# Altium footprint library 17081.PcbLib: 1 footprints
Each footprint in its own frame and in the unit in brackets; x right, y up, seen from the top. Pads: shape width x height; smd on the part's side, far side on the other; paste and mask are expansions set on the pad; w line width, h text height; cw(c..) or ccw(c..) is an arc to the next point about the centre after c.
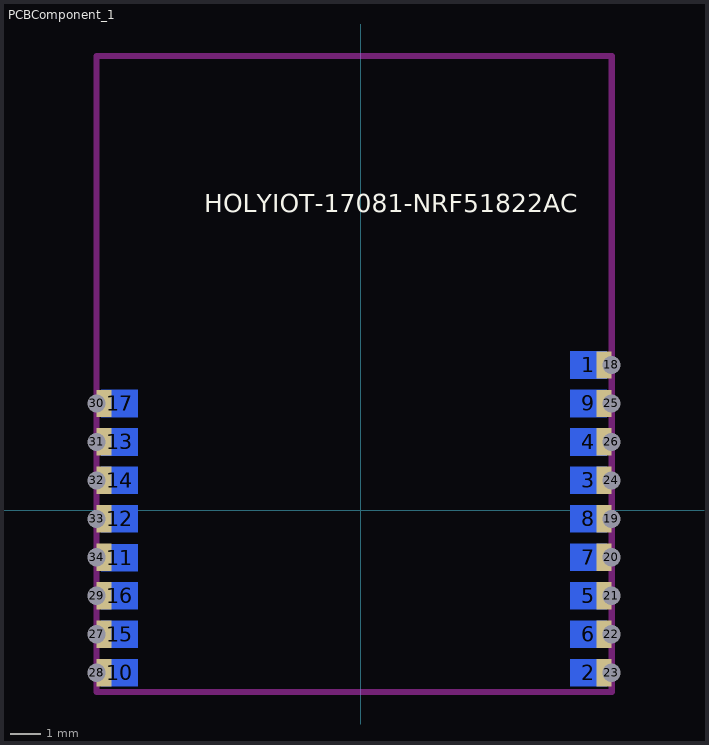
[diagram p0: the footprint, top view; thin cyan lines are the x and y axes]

## PCBComponent_1 [mm]
pads (34):
  rect 1.2x0.9 smd far side: 1(7.516,4.802) 2(7.516,-5.358) 3(7.516,0.992) 4(7.516,2.262) 5(7.516,-2.818) 6(7.516,-4.088) 7(7.516,-1.548) 8(7.516,-0.278) 9(7.516,3.532) 10(-7.954,-5.358) 11(-7.954,-1.558) 12(-7.954,-0.278) 13(-7.954,2.262) 14(-7.954,0.992) 15(-7.954,-4.088) 16(-7.954,-2.818) 17(-7.954,3.532)
  rect 0.5x0.9 hole 0.6 copper offset -0.25,0: 18(8.276,4.802) 19(8.276,-0.278) 20(8.276,-1.548) 21(8.276,-2.818) 22(8.276,-4.088) 23(8.276,-5.358) 24(8.276,0.992) 25(8.276,3.532) 26(8.276,2.262)
  rect 0.5x0.9 hole 0.6 copper offset 0.25,0: 27(-8.714,-4.088) 28(-8.714,-5.358) 29(-8.714,-2.818) 30(-8.714,3.532) 31(-8.714,2.262) 32(-8.714,0.992) 33(-8.714,-0.278) 34(-8.714,-1.548)
Top Layer:
  lines w0.2: 7.995,4.802 8.276,4.802
Top Overlay:
  text "HOLYIOT-17081-NRF51822AC" at -5.154,9.842 h0.6
Keep-Out Layer:
  lines w0.2: -8.714,-5.998 -8.714,15.002 8.286,15.002 8.286,-5.998 -8.714,-5.998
